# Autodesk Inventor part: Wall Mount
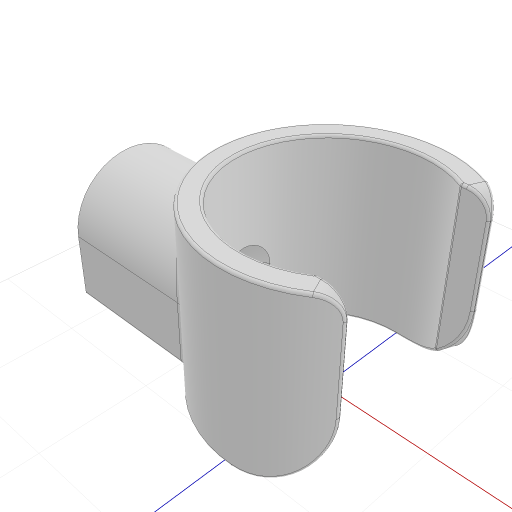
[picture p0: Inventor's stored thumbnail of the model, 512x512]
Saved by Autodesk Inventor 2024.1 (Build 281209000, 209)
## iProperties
Created: 2025-09
Part Number: Wall Mount
Material: Generic
Document SubType Name: Modeling
Designer: samue
Density: 1 g/cm^3
Appearance: Default
Author: samue
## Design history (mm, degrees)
sketch "Sketch1" dims "d0" = 36
  geometry: L1 (0, 22)-(-10, 22); L2 (-10, 22)-(-10, -25.566); L3 (-10, -14.967)-(-26.078, -14.967); L4 (-26.078, -14.967)-(-26.078, 14.966); L5 (-26.078, 14.966)-(-10, 14.966); L6 (-10, 14.966)-(-10, -14.967); L7 (46, -12.5)-(16, -12.5); L8 (16, -12.5)-(16, 12.5); L9 (16, 12.5)-(46, 12.5); L10 (46, 12.5)-(46, -12.5); A1 r 22 centre (0, 0) between (0, 22) and (22, 0); 10 further points
  constraints: 20 end point, 4 parallel, 3 horizontal, 2 coincident, 2 perpendicular, 2 point on circle, 1 centre point, 1 point on line, 1 tangent, 1 vertical, 3 other
  dimensions: "d1" = 44 diameter of A1; "d2" = 10 distance of L1.start L1.end; "d18" = 29.933 distance of L3.end L4.end; "d30" = 30 distance of L8.end L9.end; "d31" = 25 distance of L7.end L8.end
extrude "Extrusion1" new body sketch "Sketch1" distance "d4" = 35; taper "d5" = 0 deg
sketch "Sketch4" dims "d33" = 42
  geometry: L1 (16, -12.5)-(46, -12.5); L2 (46, -12.5)-(46, 12.5); L3 (46, 12.5)-(16, 12.5); L4 (16, 12.5)-(16, -12.5) reference; C1 r 18 at (0, 0); 5 further points
  constraints: 8 end point, 2 coincident, 2 parallel, 1 centre point, 1 horizontal, 1 perpendicular, 1 vertical, 3 other
  dimensions: "d32" = 36 diameter of C1; "d34" = 30 distance of L3.end L2.end; "d35" = 25 distance of L2.end L1.end
extrude "Extrusion4" join sketch "Sketch4" distance "d36" = 25; taper "d37" = 0 deg
fillet "Fillet5" dims "d38" = 12.5
chamfer "Chamfer2" distance "d19" = 1; stored, may be unused: second distance "d20" = 2, angle "d21" = 45 deg
fillet "Fillet3" dims "d17" = 15
fillet "Fillet4" dims "d22" = 4
fillet "Fillet2" dims "d13" = 0.5
sketch "Sketch5"
  geometry: L1 (0, 0)-(0, 0); L2 (17.997, -12)-(-17.997, -12) reference; C1 r 2.25 at (0, 0); 1 further point
  constraints: 2 end point, 1 centre point, 1 coincident, 1 vertical
  dimensions: "d39" = 0 distance of L1.start L1.end; "d41" = 4.5 diameter of C1
extrude "Extrusion5" cut sketch "Sketch5" stored distance "d43" = 25; taper "d44" = 0 deg
chamfer "Chamfer3" distance "d45" = 3; stored, may be unused: second distance "d46" = 2, angle "d47" = 45 deg
body "Solid1"
